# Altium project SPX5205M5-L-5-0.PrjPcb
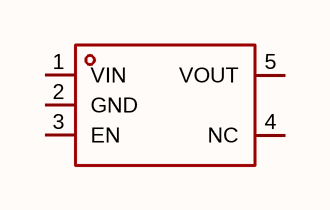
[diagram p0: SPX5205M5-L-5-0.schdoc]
1 sheet, 1 parts. Net scope: global (net labels, ports and power ports of the same name join across sheets).

## Sheet SPX5205M5-L-5-0.schdoc
size 127 x 101 mm

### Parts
U?  spx5205m5-l-5-0  [SOT-23-5_L2.9-W1.6-P0.95-LS2.8-BR]  (value not drawn)

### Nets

Not connected (* = marked no-connect by the designer): U? 1(VIN) 2(GND) 3(EN) 4(NC) 5(VOUT)

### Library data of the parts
U? = spx5205m5-l-5-0: 输出极性:正极;工作电压:20V;输出电压:5V;输出电流:150mA;电源纹波抑制比(PSRR):70dB@(1kHz);输出类型:固定;; Manufacturer: TECH PUBLIC(台舟); AddInBom: yes; ModelId: 7ba65df16e7b4570af156e925f9c37fe; ModelTransform: 114.173,114.173,0,90,0,0,0,0,0; Output Configuration: 正极; Voltage - Supply: 20V; Output Voltage: 5V; Output Current: 150mA; Voltage Dropout: 180mV@(50mA); standby current: 2uA; Output Type: 固定; Number of Outputs: 1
